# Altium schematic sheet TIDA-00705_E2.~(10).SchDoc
size 431 x 381 mm; Date: Not shown in title block; ApprovedBy: Not shown in title block; CheckedBy: Not shown in title block; Author: Ramkumar S; CompanyName: Not shown in title block; DrawnBy: Ramkumar S; Engineer: Ramkumar S; Organization: Not shown in title block; Address1: Not shown in title block; Address2: Not shown in title block; Address3: Not shown in title block; Address4: Not shown in title block; DocumentNumber: 1; Revision: Use project parameter SCH_Rev; SheetNumber: 2; SheetTotal: 3; PageSetup: Record=PageOptions¦CenterHorizontal=True¦CenterVertical=True¦PrintScale=1.00¦XCorrection=1.00¦YCorrection=1.00¦PrintKind=0¦BorderSize=5000000¦LeftOffset=0¦BottomOffset=0¦Orientation=2¦PaperLength=1000¦PaperWidth=1000¦Scale=100¦PaperSource=15¦PrintQuality=600¦MediaType=1¦DitherType=10¦PaperKind=Letter¦PrintScaleMode=1
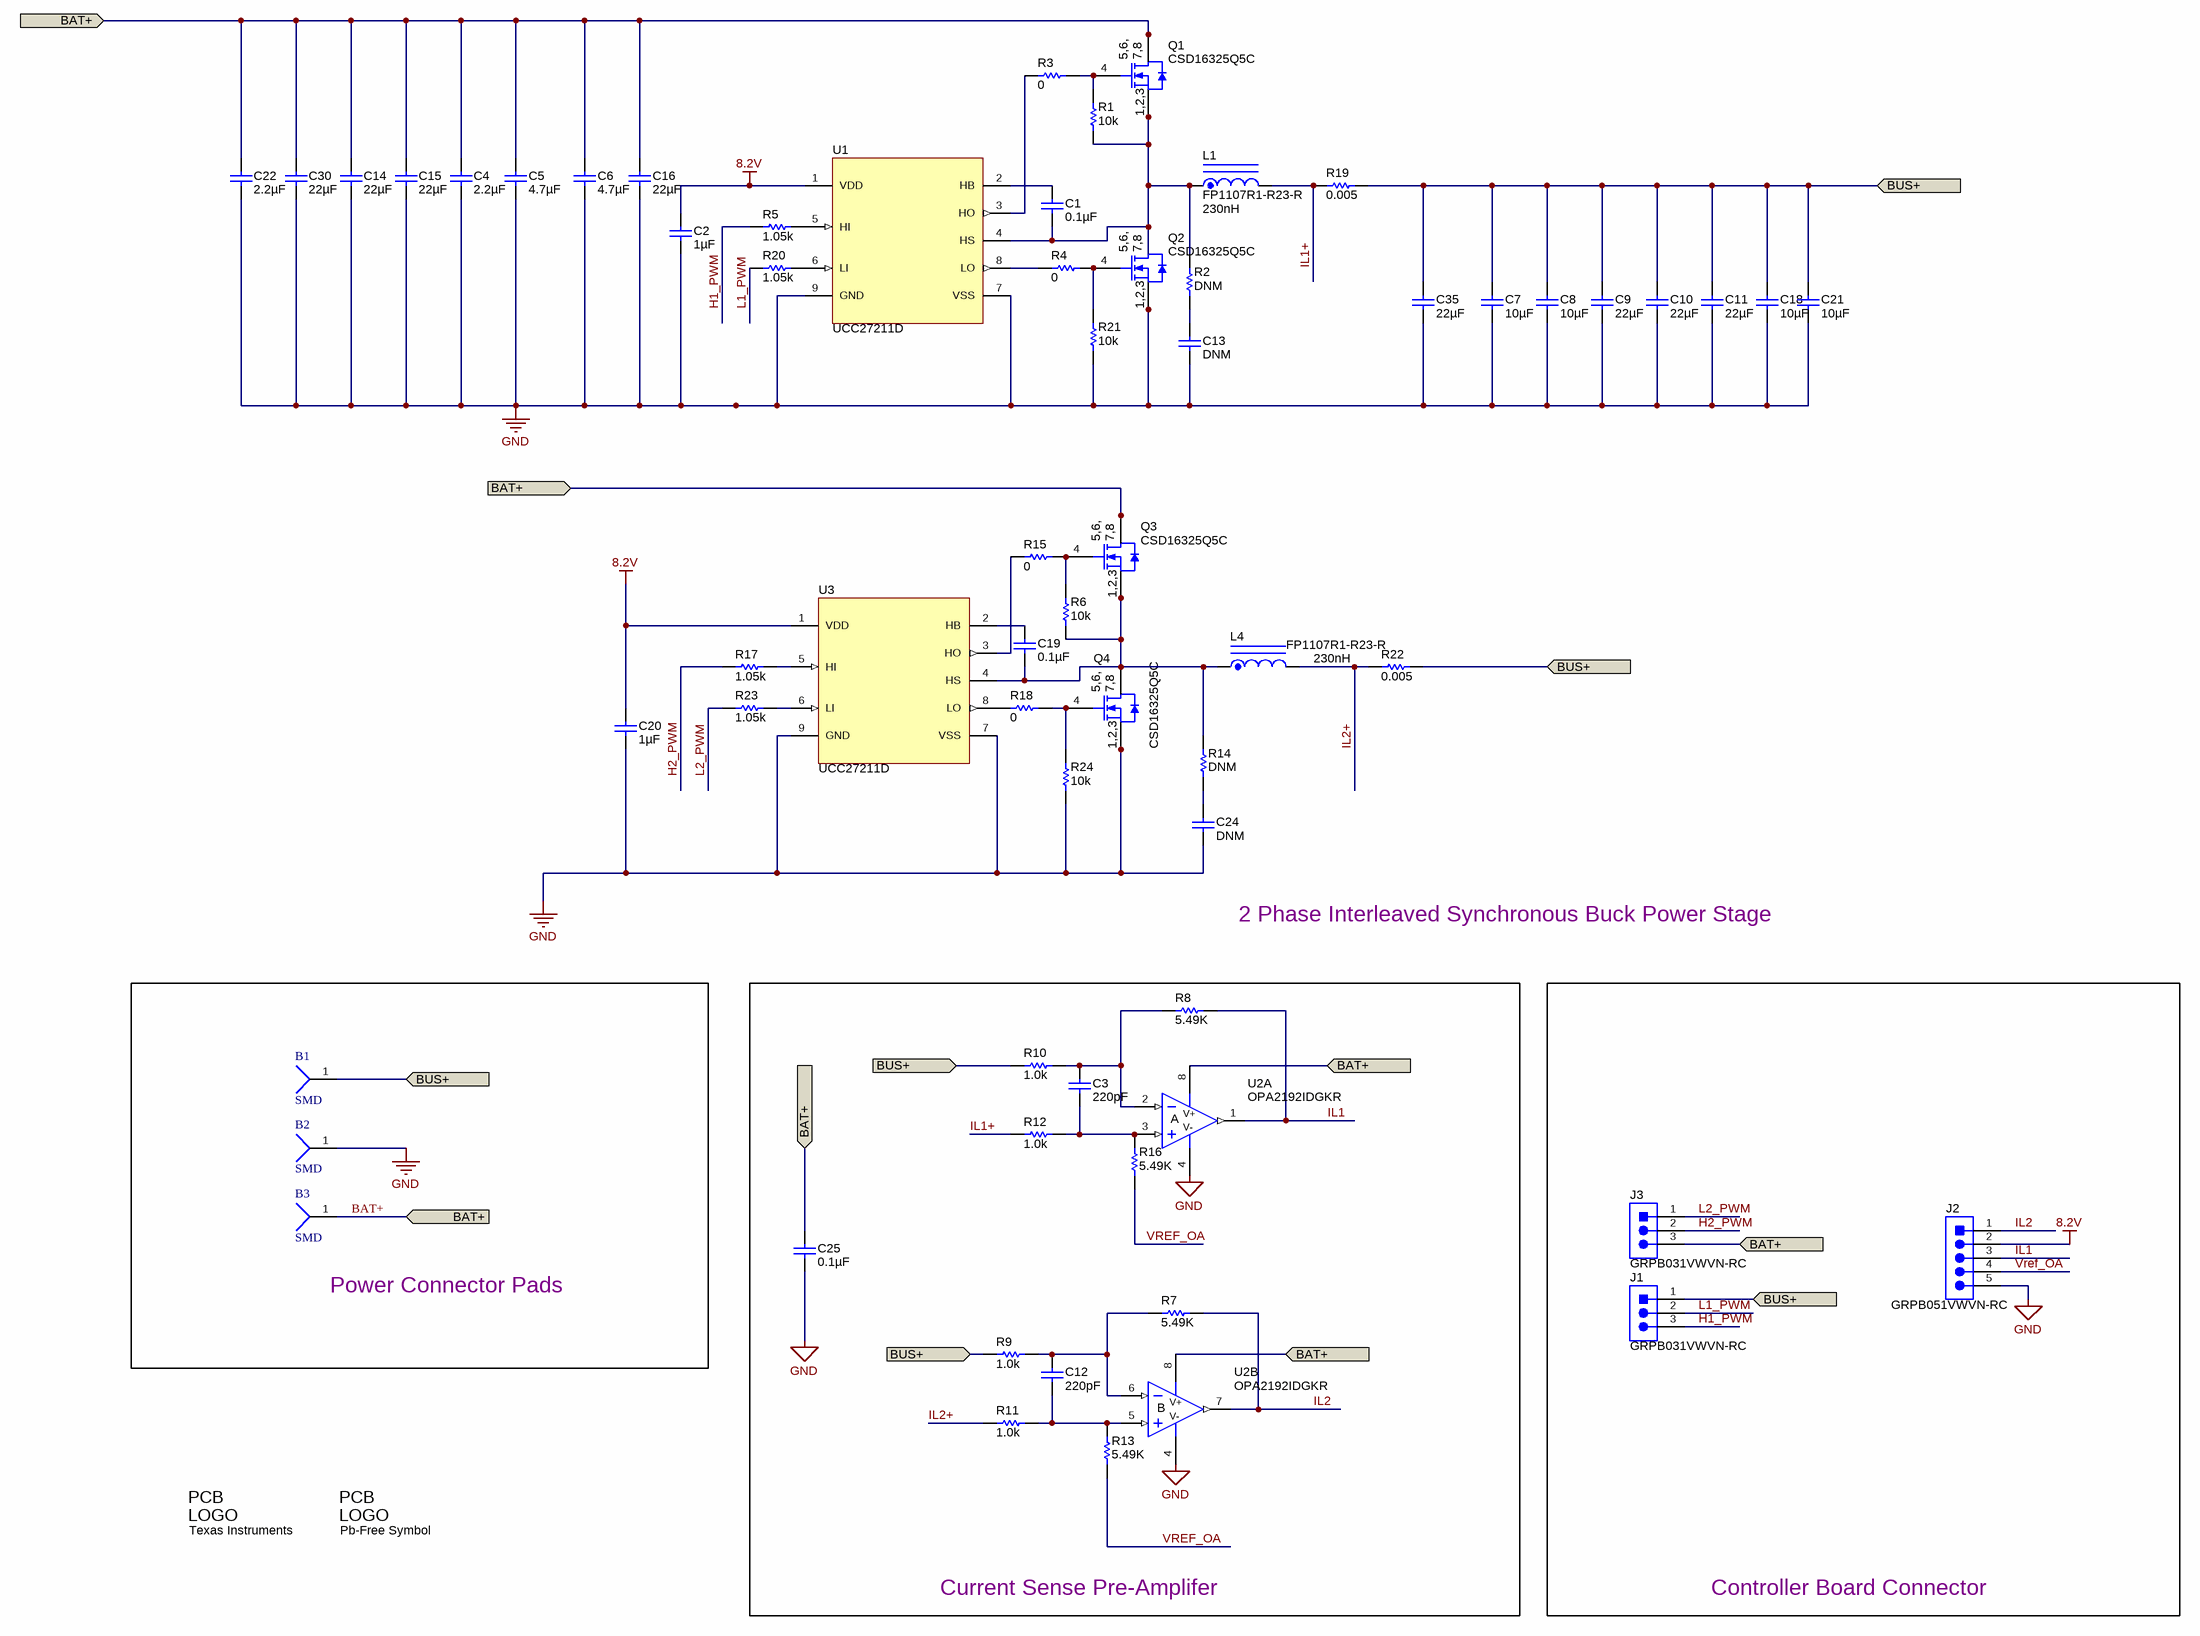
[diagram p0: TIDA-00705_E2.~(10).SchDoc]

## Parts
B1  SMD  [B1]
B2  SMD  [B1]
B3  SMD  [B1]
C1  ValueDisplayed: 0.1µF  [0402]  (hidden comment: 06033C104JAT2A)
C2  ValueDisplayed: 1µF  [0402]  (hidden comment: GRM188R61E105KA12D)
C3  ValueDisplayed: 220pF  [0402]  (hidden comment: 885012205031)
C4  ValueDisplayed: 2.2µF  [0805_HV]  (hidden comment: C2012X7R1V225K085AC)
C5  ValueDisplayed: 4.7µF  [1206]  (hidden comment: C3216X7R1E475M)
C6  ValueDisplayed: 4.7µF  [1206]  (hidden comment: C3216X7R1E475M)
C7  ValueDisplayed: 10µF  [1206_190]  (hidden comment: 12103C106KAT2A)
C8  ValueDisplayed: 10µF  [1206_190]  (hidden comment: 12103C106KAT2A)
C9  ValueDisplayed: 22µF  [1210_280]  (hidden comment: C3225X7R1C226K250AC)
C10  ValueDisplayed: 22µF  [1210_280]  (hidden comment: C3225X7R1C226K250AC)
C11  ValueDisplayed: 22µF  [1210_280]  (hidden comment: C3225X7R1C226K250AC)
C12  ValueDisplayed: 220pF  [0402]  (hidden comment: 885012205031)
C13  ValueDisplayed: DNM  [0603]  (hidden comment: 06031C222KAT2A)
C14  ValueDisplayed: 22µF  [1210_280]  (hidden comment: C3225X7R1C226K250AC)
C15  ValueDisplayed: 22µF  [1210_280]  (hidden comment: C3225X7R1C226K250AC)
C16  ValueDisplayed: 22µF  [1210_280]  (hidden comment: C3225X7R1C226K250AC)
C18  ValueDisplayed: 10µF  [0805]  (hidden comment: 12103C106KAT2A)
C19  ValueDisplayed: 0.1µF  [0402]  (hidden comment: 06033C104JAT2A)
C20  ValueDisplayed: 1µF  [0402]  (hidden comment: GRM188R61E105KA12D)
C21  ValueDisplayed: 10µF  [0805]  (hidden comment: 12103C106KAT2A)
C22  ValueDisplayed: 2.2µF  [0805_HV]  (hidden comment: C2012X7R1V225K085AC)
C24  ValueDisplayed: DNM  [0603]  (hidden comment: 06031C222KAT2A)
C25  ValueDisplayed: 0.1µF  [0402]  (hidden comment: C0603C104Z4VACTU)
C30  ValueDisplayed: 22µF  [1210_280]  (hidden comment: C3225X7R1C226K250AC)
C35  ValueDisplayed: 22µF  [1210_280]  (hidden comment: C3225X7R1C226K250AC)
J1  GRPB031VWVN-RC  [Sullins_GRPB031VWVN-RC]
J2  GRPB051VWVN-RC  [Sullins_GRPB051VWVN-RC]
J3  GRPB031VWVN-RC  [Sullins_GRPB031VWVN-RC]
L1  FP1107R1-R23-R  ValueDisplayed: 230nH  [FP1107R1]
L4  FP1107R1-R23-R  ValueDisplayed: 230nH  [FP1107R1]
Logo1  Texas Instruments  [TI_Symbol_Overlay_Small]  (no BOM)
Logo2  Pb-Free Symbol  [Pb-Free_Overlay_Small]  (no BOM)
Q1  CSD16325Q5C  [TRANS_NexFET_Q5C]
Q2  CSD16325Q5C  [TRANS_NexFET_Q5C]
Q3  CSD16325Q5C  [TRANS_NexFET_Q5C]
Q4  CSD16325Q5C  [TRANS_NexFET_Q5C]
R1  ValueDisplayed: 10k  [0402]  (hidden comment: CRCW040210K0JNED)
R2  ValueDisplayed: DNM  [0805_HV]  (hidden comment: RR1220Q-100-D)
R3  ValueDisplayed: 0  [0402]  (hidden comment: CRCW04020000Z0ED)
R4  ValueDisplayed: 0  [0402]  (hidden comment: CRCW04020000Z0ED)
R5  ValueDisplayed: 1.05k  [0402]  (hidden comment: CRCW04021K05FKED)
R6  ValueDisplayed: 10k  [0402]  (hidden comment: CRCW040210K0JNED)
R7  ValueDisplayed: 5.49K  [0402]  (hidden comment: ERA-2AEB5491X)
R8  ValueDisplayed: 5.49K  [0402]  (hidden comment: ERA-2AEB5491X)
R9  ValueDisplayed: 1.0k  [0402]  (hidden comment: RT0402BRD071KL)
R10  ValueDisplayed: 1.0k  [0402]  (hidden comment: RT0402BRD071KL)
R11  ValueDisplayed: 1.0k  [0402]  (hidden comment: RT0402BRD071KL)
R12  ValueDisplayed: 1.0k  [0402]  (hidden comment: RT0402BRD071KL)
R13  ValueDisplayed: 5.49K  [0402]  (hidden comment: ERA-2AEB5491X)
R14  ValueDisplayed: DNM  [0805_HV]  (hidden comment: RR1220Q-100-D)
R15  ValueDisplayed: 0  [0402]  (hidden comment: CRCW04020000Z0ED)
R16  ValueDisplayed: 5.49K  [0402]  (hidden comment: ERA-2AEB5491X)
R17  ValueDisplayed: 1.05k  [0402]  (hidden comment: CRCW04021K05FKED)
R18  ValueDisplayed: 0  [0402]  (hidden comment: CRCW04020000Z0ED)
R19  ValueDisplayed: 0.005  [0612]  (hidden comment: PRL1632-R005-F-T1)
R20  ValueDisplayed: 1.05k  [0402]  (hidden comment: CRCW04021K05FKED)
R21  ValueDisplayed: 10k  [0402]  (hidden comment: CRCW040210K0JNED)
R22  ValueDisplayed: 0.005  [0612]  (hidden comment: PRL1632-R005-F-T1)
R23  ValueDisplayed: 1.05k  [0402]  (hidden comment: CRCW04021K05FKED)
R24  ValueDisplayed: 10k  [0402]  (hidden comment: CRCW040210K0JNED)
U1  UCC27211D  [DRM0008A]
U2  OPA2192IDGKR  [DGK0008A_N]  (parts A,B of 2)
U3  UCC27211D  [DRM0008A]

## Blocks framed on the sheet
Power Connector Pads: B1-B3
Current Sense Pre-Amplifer: C3 C12 C25 R7-R13 R16 U2
Controller Board Connector: J1-J3

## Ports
BAT+ (in), BUS+ (in)

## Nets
8.2V: C2.1 C20.1 J2.2 U1.1(VDD) U3.1(VDD)
GND: B2.1 C2.2 C4.2 C5.2 C6.2 C7.2 C8.2 C9.2 C10.2 C11.2 C13.2 C14.2 C15.2 C16.2 C18.2 C20.2 C21.2 C22.2 C24.2 C25.2 C30.2 C35.2 J2.5 Q2.1(S) Q2.2(S) Q2.3(S) Q4.1(S) Q4.2(S) Q4.3(S) R21.1 R24.1 U1.7(VSS) U1.9(GND) U2.4(V-) U3.7(VSS) U3.9(GND)
BAT+: B3.1 C4.1 C5.1 C6.1 C14.1 C15.1 C16.1 C22.1 C25.1 C30.1 J3.3 Q1.5(D) Q1.6(D) Q1.7(D) Q1.8(D) Q1.10(D) Q3.5(D) Q3.6(D) Q3.7(D) Q3.8(D) Q3.10(D) U2.8(V+) ; port BAT+
BUS+: B1.1 C7.1 C8.1 C9.1 C10.1 C11.1 C18.1 C21.1 C35.1 J1.1 R9.1 R10.1 R19.2 R22.2 ; port BUS+
H1_PWM: J1.3 R5.2
H2_PWM: J3.2 R17.2
IL1: J2.3 R8.2 U2.1(OUT)
IL1+: L1.2 R12.1 R19.1
IL2: J2.1 R7.2 U2.7(OUT)
IL2+: L4.2 R11.1 R22.1
L1_PWM: J1.2 R20.2
L2_PWM: J3.1 R23.2
VREF_OA: J2.4 R13.1 R16.1
NetC1_1: C1.1 U1.2(HB)
NetC1_2: C1.2 L1.1 Q1.1(S) Q1.2(S) Q1.3(S) Q2.5(D) Q2.6(D) Q2.7(D) Q2.8(D) Q2.10(D) R1.1 R2.2 U1.4(HS)
NetC3_1: C3.1 R8.1 R10.2 U2.2(IN-)
NetC3_2: C3.2 R12.2 R16.2 U2.3(IN+)
NetC12_1: C12.1 R7.1 R9.2 U2.6(IN-)
NetC12_2: C12.2 R11.2 R13.2 U2.5(IN+)
NetC13_1: C13.1 R2.1
NetC19_1: C19.1 U3.2(HB)
NetC19_2: C19.2 L4.1 Q3.1(S) Q3.2(S) Q3.3(S) Q4.5(D) Q4.6(D) Q4.7(D) Q4.8(D) Q4.10(D) R6.1 R14.2 U3.4(HS)
NetC24_1: C24.1 R14.1
NetQ1_4: Q1.4(G) R1.2 R3.2
NetQ2_4: Q2.4(G) R4.2 R21.2
NetQ3_4: Q3.4(G) R6.2 R15.2
NetQ4_4: Q4.4(G) R18.2 R24.2
NetR3_1: R3.1 U1.3(HO)
NetR4_1: R4.1 U1.8(LO)
NetR5_1: R5.1 U1.5(HI)
NetR15_1: R15.1 U3.3(HO)
NetR17_1: R17.1 U3.5(HI)
NetR18_1: R18.1 U3.8(LO)
NetR20_1: R20.1 U1.6(LI)
NetR23_1: R23.1 U3.6(LI)

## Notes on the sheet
- 2 Phase Interleaved Synchronous Buck Power Stage

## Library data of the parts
B1-B3 = TP_30X40MIL: Test Point, SM, 2x3mm
C1 C19 = 06033C104JAT2A: CAP, CERM, 0.1 µF, 25 V, +/- 5%, X7R, 0603; Manufacturer: AVX; Polarized: N; CompType: Capacitor; Value: 0.1uF; U/M: EA; Cap_F: 0.0000001; Tolerance_%: 5; ESR_ohm: 0.05; Value1: 0.05 ohm; VDC_V: 25; Value2: 25V; TaMin_C: -55; TaMax_C: 125; Cap_Case: 0603
C2 C20 = GRM188R61E105KA12D: CAP, CERM, 1 µF, 25 V, +/- 10%, X5R, 0603; Manufacturer: MuRata; Polarized: N; CompType: Capacitor; Value: 1uF; U/M: EA; Cap_F: 0.000001; Tolerance_%: 10; Value1: Unknown; VDC_V: 25; Value2: 25V; TaMin_C: -55; TaMax_C: 85; Cap_Case: 0603
C3 C12 = 885012205031: CAP, CERM, 0.01 µF, 16 V, +/- 10%, X7R, 0402; Manufacturer: Wurth Elektronik; Polarized: N; CompType: Capacitor; Value: 220pF; U/M: EA; Cap_F: 0.00000001; Tolerance_%: 10; Value1: Unknown; VDC_V: 16; Value2: 16V; TaMin_C: -55; TaMax_C: 125; AEC Category: Q200
C4 C22 = C2012X7R1V225K085AC: CAP, CERM, 2.2 µF, 35 V, +/- 10%, X7R, 0805; Manufacturer: TDK; Polarized: N; CompType: Capacitor; Value: 2.2uF; U/M: EA; Cap_F: 0.0000022; Tolerance_%: 10; Value1: Unknown; VDC_V: 35; Value2: 35V; TaMin_C: -55; TaMax_C: 125; Cap_Case: 0805
C5 C6 = C3216X7R1E475M: CAP, CERM, 4.7 µF, 25 V, +/- 20%, X7R, 1206; Manufacturer: TDK; Polarized: N; CompType: Capacitor; Value: 4.7uF; U/M: EA; Cap_F: 0.0000047; Tolerance_%: 20; ESR_ohm: 0.0063; Value1: 0.0063 ohm; VDC_V: 25; Value2: 25V; TaMin_C: -55; TaMax_C: 125
C7 C8 C18 C21 = 12103C106KAT2A: CAP, CERM, 10 µF, 25 V, +/- 10%, X7R, 1210; Manufacturer: AVX; Polarized: N; CompType: Capacitor; Value: 10uF; U/M: EA; Cap_F: 0.00001; Tolerance_%: 10; Value1: Unknown; VDC_V: 25; Value2: 25V; TaMin_C: -55; TaMax_C: 125; Cap_Case: 1210
C9-C11 C14-C16 C30 C35 = C3225X7R1C226K250AC: CAP, CERM, 22 µF, 16 V, +/- 10%, X7R, 1210; Manufacturer: TDK; Polarized: N; CompType: Capacitor; Value: 22uF; U/M: EA; Cap_F: 0.000022; Tolerance_%: 10; Value1: Unknown; VDC_V: 16; Value2: 16V; TaMin_C: -55; TaMax_C: 125; Cap_Case: 1210
C13 C24 = 06031C222KAT2A: CAP, CERM, 2200 pF, 100 V, +/- 10%, X7R, 0603; Manufacturer: AVX; Polarized: N; CompType: Capacitor; Value: DNM; U/M: EA; Cap_F: 0.0000000022; Tolerance_%: 10; ESR_ohm: 0.192; Value1: 0.192 ohm; VDC_V: 100; Value2: 100V; TaMin_C: -55; TaMax_C: 125; AEC Category: Q200
C25 = C0603C104Z4VACTU: CAP, CERM, 0.1 µF, 16 V, +80/-20%, Y5V, 0603; Manufacturer: Kemet; Polarized: N; CompType: Capacitor; Value: 0.1uF; U/M: EA; Cap_F: 0.0000001; Tolerance_%: 80; Value1: Unknown; VDC_V: 16; Value2: 16V; TaMin_C: -30; TaMax_C: 85; Cap_Case: 0603
J1 J3 = GRPB031VWVN-RC: Header, 50mil, 3x1, Gold, TH; Manufacturer: Sullins Connector Solutions; SymbolCreator: a0799628; Gender: Male; Shrouded: N; Row_Count: 1
J2 = GRPB051VWVN-RC: Header, 50mil, 5x1, Gold, TH; Manufacturer: Sullins Connector Solutions; SymbolCreator: a0412235
L1 L4 = FP1107R1-R23-R: Inductor, Wirewound, Ferrite, 230nH, 45A, 0.00029 ohm, SMD; Manufacturer: Coiltronics; SymbolCreator: a0412235; Ind_H: 230.0E-9; Imax_A: 45; Irms: 55A @ 40C rise; Isat: 45A @ 20% inductance drop; U/M: EA
Logo1 = TI_Logo: Texas Instrument Corporate Signature; SymbolCreator: codlsc
Logo2 = Pb-Free: SymbolCreator: a0412235
Q1-Q4 = CSD16325Q5C: MOSFET, N-CH, 25 V, 100 A, DualCool SON 5x6mm; Manufacturer: Texas Instruments; Alternate Manufacturer: None; U/M: EA; ChType: N; Value: 25V; VdsMax_V: 25; Value1: 0.0017 ohm; Rdson45_ohm: 0.0017; Value2: 18 nC; QgTyp_nC: 18; Vgs_V: 10; IdsMax_A: 100
R1 R6 R21 R24 = CRCW040210K0JNED: RES, 10 k, 5%, 0.063 W, 0402; Manufacturer: Vishay-Dale; CompType: Resistor; Value: 10k; Res_ohm: 10000; Value_Code: 10k0; Tolerance_%: 5; Power_W: 0.063; Value2: 0.063W; VDC_V: 50; TempCo: 200 ppm/C; EIA_Code: E24; U/M: EA
R2 R14 = RR1220Q-100-D: RES, 10.0, 0.5%, 0.1 W, 0805; Manufacturer: Susumu Co Ltd; CompType: Resistor; Value: DNM; Res_ohm: 10; Value_Code: 10R0; Tolerance_%: 0.5; Power_W: 0.1; Value2: 0.1W; VDC_V: 100; TempCo: 50 ppm/C; EIA_Code: E192; U/M: EA; AEC Category: Q200
R3 R4 R15 R18 = CRCW04020000Z0ED: RES, 0, 5%, 0.063 W, 0402; Manufacturer: Vishay-Dale; CompType: Resistor; Value: 0; Value_Code: 0000; Tolerance_%: 5; Power_W: 0.063; Value2: 0.063W; VDC_V: 50; TempCo: 200 ppm/C; EIA_Code: E24; U/M: EA; AEC Category: Q200
R5 R17 R20 R23 = CRCW04021K05FKED: RES, 1.05 k, 1%, 0.063 W, 0402; Manufacturer: Vishay-Dale; CompType: Resistor; Value: 1.05k; Res_ohm: 1050; Value_Code: 1k05; Tolerance_%: 1; Power_W: 0.063; Value2: 0.063W; VDC_V: 50; TempCo: 100 ppm/C; EIA_Code: E96; U/M: EA
R7 R8 R13 R16 = CRCW04021K05FKED: RES, 5.49 k, 0.1%, 0.063 W, 0402; Manufacturer: Panasonic Electronic Corporation; CompType: Resistor; Value: 5.49K; Res_ohm: 5490; Tolerance_%: 1; Power_W: 0.063; Value2: 0.063W; VDC_V: 50; TempCo: 100 ppm/C; EIA_Code: E96; U/M: EA
R9-R12 = CRCW04021K05FKED: RES, 1.0 k, 0.1%, 0.063 W, 0402; Manufacturer: Vishay-Dale; CompType: Resistor; Value: 1.0k; Res_ohm: 1050; Value_Code: 1k; Tolerance_%: 1; Power_W: 0.063; Value2: 0.063W; VDC_V: 50; TempCo: 100 ppm/C; EIA_Code: E96; U/M: EA
R19 R22 = PRL1632-R005-F-T1: RES, 0.0005, 1%, 1 W, 0612; Manufacturer: Susumu Co Ltd; CompType: Resistor; Value: 0.005; Res_ohm: 0.0005; Value_Code: 5L000; Tolerance_%: 1; Value2: 1W; TempCo: 350 ppm/C; EIA_Code: E96; U/M: EA
U1 U3 = UCC27211D: 120-V Boot, 4-A Peak, High Frequency High-Side and Low-Side Driver, D0008A; Manufacturer: Texas Instruments; SymbolCreator: Altium; CompType: IC; U/M: EA
U2 = OPA2192IDGKR: 36-V, Precision, Rail-to-Rail Input/Output, Low Offset Voltage, Low Input Bias Current Op Amp with e-trim, DGK0008A; Manufacturer: Texas Instruments; CompType: IC; U/M: EA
